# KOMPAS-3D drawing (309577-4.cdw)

Referenced files: вид спереди.cdw
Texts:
  КГТУ 00.00.000 ВО
  Колонна абсорбционная  @2~1400 Чертеж общего вида
  Текст на чертеже
  Размерные надписи
  Шероховатость
  Линия-выноска #1
  Линия-выноска #2
  Линия-выноска #3
  Отклонения формы и база
  Заголовок таблицы
  Ячейка таблицы
  Стрелка вида
  Обозначение изменения
  Фигурная скобка
  Номер узла
  Марка координационной оси
  VRCB
  Выносная надпись
  Обозначение узла
  Марка/позиционное обозначение с линией-выноской
  Марка/позиционное обозначение на линии
  Марка/позиционное обозначение без линии-выноски
  <template><curves><curve offset="10.000000"><style id="0" type="0"/></curve><curve offset="0.000000"><style id="2" type="0"/></curve><curve offset="-10.000000"><style id="0" type="0"/></curve></curves><tips><begin type="0" param="50.000000"><style id="0" type="0"/></begin><end type="0" param="50.000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
  Приложение 2
  Кол.
  Проход усл. Dу,
  Давление усл. Pу,
  МПа
  Вход газовой смеси
  Выход газовой смеси
  Вход жидкости
  Выход жидкости
  Для манометра
  Для термометра
  Люк
  Техническая характеристика
  1. Аппарат предназначен для разделения газовой смеси азот-вода.
  2. Производительность 3,6 кг/с.
  3. Давление в колонне - атмосферное.
  4. Температура среды в кубе - 20 С.
  5. Среда в аппарате - токсичная, корозионная.
  6. Тип колонны - насадочная.
  7. Высота насадки 10м.
  Технические требования
  1. При изготовлении, испытании и постановке аппарата должны выполняться
  требованя:
  2. Материал деталей колонны, соприкасающихся с разделительными жидкостями,
  - сталь Х18Н10Т ГОСТ 5632-72, остальных - сталь Ст3 ГОСТ 380-71.
  3. Аппарат испытать на прочность и плотность гидравлически в горизонтальном
  положении давлением 0,2МПа, в вертикальном положении - наливом.
  4. Сварные соединения должны соответствовать требованиям
  ОСТ 26-01-82-77 "Сварка в химическом машиностроении".
  5. Сварные швы в объеме 100% контролировать рентгенопросвчиванием.
  6. Размеры для справок.
  Уклон 1:5*
  и марка материала
  Поз.
  Колонна
  Куб
  Крышка
  Крышка люка
  Тарелка ТСН - III
  Тарелка ТСН - II
  Опора
  Гильза термометра
  Решетка
  Колльца Рашига 80 80 8
  Керамика
  Прокладка
  Паронит ПОН-1
  Колонна абсорбционная
  Чертеж общего вида
  КГТУ 00.00.000 ВО-
Dimensions and other numbers on the sheet: 7; 15660; 1400; 250; 5000; 1311; 1038; 850; 860; 820; 580; 8500; 535; 950; 327; 4; 96патрубков; 45; 80; 160; 260; 980; 22 отв.; 6; 28; 1710; 1560; 10; 27; 110 патрубков; 6 отв.; 1; 2; 50; 25; 600; 1,6; 2,5; 684; 770; 36; 20 шт.; 1 шт.; 3; 5; 8; 9; 0Х13; 11; 26; 12 отв.; 12; 1:20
